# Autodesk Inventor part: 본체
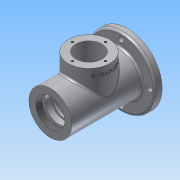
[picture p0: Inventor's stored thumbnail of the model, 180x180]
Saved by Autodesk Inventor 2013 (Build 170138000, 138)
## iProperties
Created: 2016-08
Part Number: 본체
Material: 알루미늄 6061
Document SubType Name: Modeling
Designer: Administrator
Mass: 726.591 g
Surface Area: 619.863 cm^2
Volume: 268.115 cm^3
Density: 2.71 g/cm^3
Author: Administrator
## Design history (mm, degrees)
sketch "스케치1"
  geometry: L1 (0, 0)-(115, 0); L2 (0, 0)-(0, 31); L3 (0, 31)-(102, 31); L4 (102, 31)-(102, 50); L5 (102, 50)-(112, 50); L6 (112, 50)-(112, 31); L7 (112, 31)-(115, 31); L8 (115, 31)-(115, 0)
  constraints: 16 end point, 5 perpendicular, 2 parallel, 1 collinear, 1 horizontal
  dimensions: "d0" = 115 distance of L1.start L1.end; "d1" = 62 diameter of L3 L1; "d2" = 3 distance of L6.end L7.end; "d3" = 13 distance between parallel lines of L8 L4; "d4" = 100 diameter of L5 L1
revolve "회전1" sketch "스케치1" stored, may be unused: angle "d5" = 90 deg
node "작업 평면1"
sketch "스케치2"
  geometry: L1 (0, -31)-(0, 31) reference; C1 r 30 at (56, 0); 2 further points
  constraints: 1 centre point, 1 horizontal alignment, 1 midpoint
  dimensions: "d7" = 60 diameter of C1; "d8" = 56 distance from line of C1.centre L1
extrude "돌출1" join sketch "스케치2" distance "d9" = 50; taper "d10" = 0 deg
sketch "스케치3"
  geometry: A1 r 41.5 centre (0, 0) between (0, 41.5) and (-41.5, 0); 3 further points
  constraints: 4 point on circle, 2 horizontal alignment, 2 vertical alignment, 1 centre point, 1 coincident
  dimensions: "d11" = 83 diameter of A1
hole "구멍1" sketch "스케치3" at (0, 41.5), (-41.5, 0), (0, -41.5), (41.5, 0) diameter "d12" = 8; stored, may be unused: countersink angle "d16" = 90 deg, drill point angle "d18" = 118 deg; dims "d13" = 6, "d14" = 4, "d15" = 2, "d17" = 8
sketch "스케치4"
  geometry: C1 r 30 at (0, 0) reference; A1 r 24 centre (0, 0) between (0, 24) and (-24, 0); 3 further points
  constraints: 4 point on circle, 2 horizontal alignment, 2 vertical alignment, 1 centre point, 1 coincident
  dimensions: "d19" = 48 diameter of A1
hole "구멍2" sketch "스케치4" at (0, 24), (-24, 0), (0, -24), (24, 0) diameter "d20" = 3.242; stored, may be unused: countersink angle "d24" = 90 deg, drill point angle "d26" = 118 deg; dims "d21" = 8, "d22" = 4, "d23" = 2, "d25" = 10
sketch "스케치5"
  geometry: L1 (-115, 31)-(-115, -31) reference; L2 (0, 31)-(0, -31) reference; L3 (0, 0)-(-115, 0); L4 (-115, 21)-(-101, 16); L5 (-93.7, 12.2)-(-93.7, 10); L6 (-93.7, 10)-(-91, 10); L7 (-91, 10)-(-91, 13.5); L8 (-88, 16.5)-(-86, 16.5); L9 (-86, 16.5)-(-86, 17.2); L10 (-85.7, 17.5)-(-76, 17.5); L11 (-75, 18.5)-(-75, 23); L12 (-72, 26)-(-40, 26); L13 (-37, 23)-(-37, 18.5); L14 (-36, 17.5)-(-26, 17.5); L15 (-26, 17.5)-(-26, 18.5); L16 (-26, 18.5)-(-24.25, 18.5); L17 (-24.25, 18.5)-(-24.25, 17.5); L18 (-24.25, 17.5)-(-21, 17.5); L19 (-21, 17.5)-(-21, 19.7); L20 (-20.7, 20)-(-12, 20); L21 (-12, 20)-(-12, 24); L22 (-12, 24)-(-9, 24); L23 (-9, 24)-(-9, 21); L24 (-9, 21)-(0, 21); L25 (0, 21)-(0, 0); L26 (-115, 21)-(-115, 0); L27 (-101, 16)-(-101, 12.904); L28 (-101, 12.904)-(-100.3, 12.5); L29 (-100.3, 12.5)-(-94, 12.5); L30 (-86, 49)-(-26, 49) reference; L31 (-76, 17.5)-(-75, 18.5); L32 (-37, 18.5)-(-36, 17.5); A1 r 0.3 centre (-20.7, 19.7) between (-20.7, 20) and (-21, 19.7); A2 r 0.3 centre (-94, 12.2) between (-93.7, 12.2) and (-94, 12.5); A3 r 0.3 centre (-85.7, 17.2) between (-85.7, 17.5) and (-86, 17.2); A4 r 3 centre (-88, 13.5) between (-88, 16.5) and (-91, 13.5); A5 r 3 centre (-72, 23) between (-72, 26) and (-75, 23); A6 r 3 centre (-40, 23) between (-37, 23) and (-40, 26); 7 further points
  constraints: 58 end point, 12 parallel, 12 point on circle, 12 point on line, 12 tangent, 11 perpendicular, 6 centre point, 3 equal radius, 3 midpoint, 1 collinear, 1 vertical alignment
  dimensions: "d27" = 30 deg angle of L29 L28; "d28" = 3 distance of L21.end L22.end; "d30" = 12 distance between parallel lines of L21 L25; "d31" = 21 distance between parallel lines of L19 L25; "d32" = 26 distance between parallel lines of L15 L2; "d33" = 60 distance between parallel lines of L9 L15; "d34" = 5 distance of point (-91, 16.5) L8.end; "d35" = 14 horizontal distance of L4.end L4.start; "d36" = 42 diameter of L4.start L3; "d37" = 32 diameter of L4.end L3; "d38" = 33 diameter of L8 L3; "d39" = 35 diameter of L10 L3; "d40" = 52 diameter of L12 L3; "d41" = 0.7 horizontal distance of L28.end L27.end; "d42" = 7.3 distance from line of L5 L27.end; "d43" = 38 distance of point (-75, 26) point (-37, 26); "d44" = 25 diameter of L29 L3; "d45" = 20 diameter of L6 L3; "d46" = 35 diameter of L14 L3; "d47" = 35 diameter of L18 L3; "d48" = 40 diameter of L20 L3; "d49" = 42 diameter of L24 L3; "d50" = 48 diameter of L22 L3; "d51" = 1.75 distance of L15.end L16.end; "d52" = 37 diameter of L16 L3; "d53" = 1 distance of L10.end point (-75, 17.5); "d54" = 1 distance of L11.start point (-75, 17.5) (= d53); "d55" = 1 distance of L13.end point (-37, 17.5) (= d53); "d56" = 1 distance of L14.start point (-37, 17.5) (= d55); "d57" = 0.3 radius of A1; "d58" = 3 radius of A4; "d77" = 3 radius of A5
revolve "회전2" sketch "스케치5" stored, may be unused: angle "d59" = 90 deg
feature "스레드1" dims "d60" = 10, "d61" = 0
hole "구멍3" diameter "d64" = 38; stored, may be unused: countersink angle "d68" = 90 deg, drill point angle "d70" = 0 deg; dims "d62" = 10, "d63" = 10, "d65" = 8, "d66" = 4, "d67" = 2, "d69" = 40
fillet "모깎기1" dims "d71" = 3
node "작업 평면2"
sketch "스케치6"
  geometry: L1 (35.261, 42.002)-(76.739, 42.002); L2 (76.739, 42.002)-(76.739, 35.998); L3 (76.739, 35.998)-(35.261, 35.998); L4 (35.261, 35.998)-(35.261, 42.002); L5 (0, -31)-(0, 31) reference; L6 (26, 49)-(86, 49) reference; 4 further points
  constraints: 2 midpoint, 1 horizontal alignment, 1 vertical alignment, 2 other
  dimensions: "d73" = 56 distance from line of L5 point (56, 39); "d74" = 10 distance from line of point (56, 39) L6
feature "엠보싱1" sketch "스케치6" dims "d0" = 115, "d1" = 62, "d2" = 3, "d3" = 13, "d4" = 100, "d17" = 8, "d75" = 0.5, "d76" = 0
fillet "모깎기2" dims "d78" = 3
node "솔리드1"
other parameters: "d6" = 49
